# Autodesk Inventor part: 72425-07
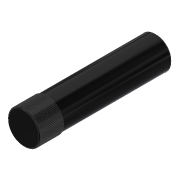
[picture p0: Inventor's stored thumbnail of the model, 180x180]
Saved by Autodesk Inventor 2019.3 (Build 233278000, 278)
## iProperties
Created: 2012-10
Part Number: 72425-07
Material: Ogólny
Document SubType Name: Modeling
Designer: CADENGINEERING4
Density: 1 g/cm^3
Appearance: Gładki — czarny
Author: CADENGINEERING4
Revision Number: ÈÎºÎ
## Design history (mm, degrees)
feature "ÊäÈë1"
node "Bryła1"
